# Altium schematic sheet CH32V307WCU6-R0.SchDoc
size 332 x 281 mm
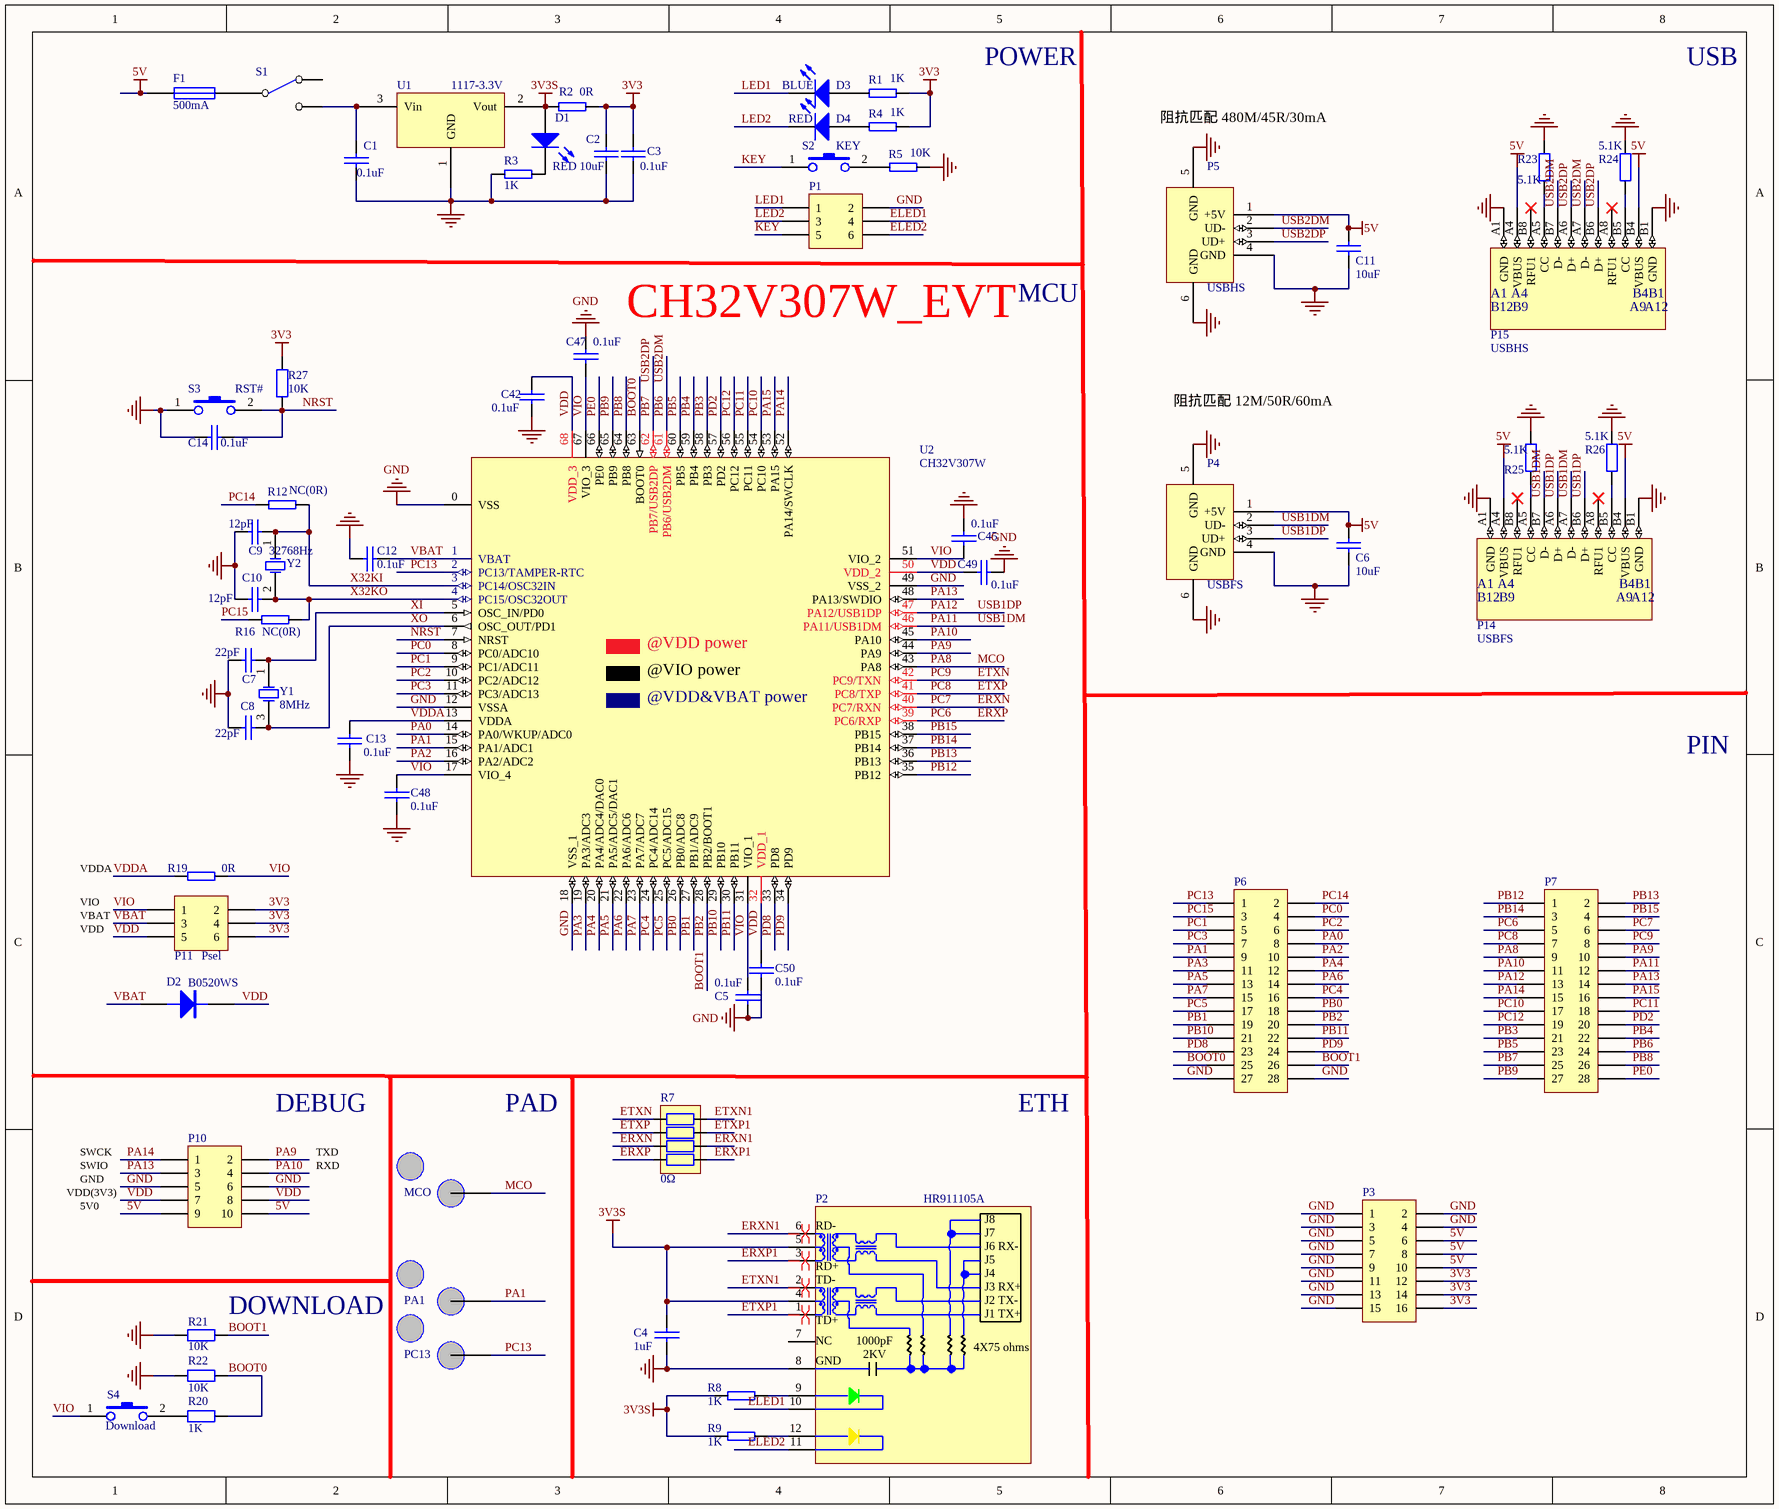
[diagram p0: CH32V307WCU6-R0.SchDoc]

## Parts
C1  0.1uF  [0603_C]
C2  10uF  [3216_C]
C3  0.1uF  [0603_C]
C4  1uF  [0603_C]
C5  0.1uF  [0603_C]
C6  10uF  [3216_C]
C7  22pF  [0603_C]
C8  22pF  [0603_C]
C9  12pF  [0603_C]
C10  12pF  [0603_C]
C11  10uF  [3216_C]
C12  0.1uF  [0603_C]
C13  0.1uF  [0603_C]
C14  0.1uF  [0603_C]
C42  0.1uF  [0603_C]
C45  0.1uF  [0603_C]
C47  0.1uF  [0603_C]
C48  0.1uF  [0603_C]
C49  0.1uF  [0603_C]
C50  0.1uF  [0603_C]
D1  RED  [0603+]
D2  B0520WS  [SOD-323]
D3  BLUE  [0603+]
D4  RED  [0603+]
F1  500mA  [0603]
MCO  Testpoint  [TESTPOINT1]  (value not drawn)
P1  IO  [IDC6-2.54mm]  (value not drawn)
P2  HR911105A  [HR911105A]
P3  Ppin  [IDC16-2.54mm]  (value not drawn)
P4  USBFS  [USBAF]
P5  USBHS  [USBAF]
P6  HEADER 14x2  [IDC28-2.54MM]  (value not drawn)
P7  HEADER 14x2  [IDC28-2.54MM]  (value not drawn)
P10  LINK  [IDC10-2.54mm]  (value not drawn)
P11  Psel  [IDC6-2.54mm]
P14  USBFS  [TYPE-C-Receptacle-2.0]
P15  USBHS  [TYPE-C-Receptacle-2.0]
PA1  Testpoint  [TESTPOINT1]  (value not drawn)
PC13  Testpoint  [TESTPOINT1]  (value not drawn)
R1  1K  [0603]
R2  0R  [0603]
R3  1K  [0603]
R4  1K  [0603]
R5  10K  [0603]
R7  0Ω  [8P4R-0603]
R8  1K  [0603]
R9  1K  [0603]
R12  NC(0R)  [0603]
R16  NC(0R)  [0603]
R19  0R  [0603]
R20  1K  [0603]
R21  10K  [0603]
R22  10K  [0603]
R23  5.1K  [0603]
R24  5.1K  [0603]
R25  5.1K  [0603]
R26  5.1K  [0603]
R27  10K  [0603]
S1  SW SPDT  [KEY2]  (value not drawn)
S2  KEY  [SMD_6.1x3.65x2.5mm-KEY]
S3  RST#  [SMD_6.1x3.65x2.5mm-KEY]
S4  Download  [SMD_6.1x3.65x2.5mm-KEY]
U1  1117-3.3V  [SOT-223]
U2  CH32V307W  [QFN68_8x8]
Y1  8MHz  [XT3225]
Y2  32768Hz  [FC-135]

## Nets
3V3: C2.1 C3.1 P3.12 P3.14 P3.16 P11.2 P11.4 P11.6 R1.1 R2.1 R4.1 R27.2
3V3S: C4.2 D1.1(A) P2.4 P2.5 R2.2 R8.1 R9.1 U1.2(Vout)
5V: C6.1 C11.1 F1.1 P3.6 P3.8 P3.10 P4.1(+5V) P5.1(+5V) P10.9 P10.10 P14.A4(VBUS) P14.B4(VBUS) P15.A4(VBUS) P15.B4(VBUS)
GND: C1.2 C2.2 C3.2 C4.1 C5.1 C6.2 C7.1 C8.1 C9.1 C10.1 C11.2 C12.1 C13.2 C14.1 C42.1 C45.2 C47.2 C48.2 C49.1 C50.2 P1.2 P2.8 P3.1 P3.2 P3.3 P3.4 P3.5 P3.7 P3.9 P3.11 P3.13 P3.15 P4.4(GND) P4.5(GND) P4.6(GND) P5.4(GND) P5.5(GND) P5.6(GND) P6.27 P6.28 P10.5 P10.6 P14.A1(GND) P14.B1(GND) P15.A1(GND) P15.B1(GND) R3.2 R5.1 R21.2 R22.2 R23.2 R24.2 R25.2 R26.2 S3.1 U1.1(GND) U2.0(VSS) U2.12(VSSA) U2.18(VSS_1) U2.49(VSS_2)
BOOT0: P6.25 R20.1 R22.1 U2.63(BOOT0)
BOOT1: P6.20 P6.26 R21.1 U2.28(PB2/BOOT1)  [also labelled PB2]
ELED1: P1.4 P2.10
ELED2: P1.6 P2.11
ERXN: P7.6 R7.3 U2.40(PC7/RXN)  [also labelled PC7]
ERXN1: P2.6 R7.6
ERXP: P7.5 R7.4 U2.39(PC6/RXP)  [also labelled PC6]
ERXP1: P2.3 R7.5
ETXN: P7.8 R7.1 U2.42(PC9/TXN)  [also labelled PC9]
ETXN1: P2.2 R7.8
ETXP: P7.7 R7.2 U2.41(PC8/TXP)  [also labelled PC8]
ETXP1: P2.1 R7.7
KEY: P1.5 S2.1
LED1: D3.2(K) P1.1
LED2: D4.2(K) P1.3
MCO: MCO.1(point) P7.9 U2.43(PA8)  [also labelled PA8]
NRST: C14.2 R27.1 S3.2 U2.7(NRST)
PA0: P6.8 U2.14(PA0/WKUP/ADC0)
PA1: P6.9 PA1.1(point) U2.15(PA1/ADC1)
PA2: P6.10 U2.16(PA2/ADC2)
PA3: P6.11 U2.19(PA3/ADC3)
PA4: P6.12 U2.20(PA4/ADC4/DAC0)
PA5: P6.13 U2.21(PA5/ADC5/DAC1)
PA6: P6.14 U2.22(PA6/ADC6)
PA7: P6.15 U2.23(PA7/ADC7)
PA9: P7.10 P10.2 U2.44(PA9)
PA10: P7.11 P10.4 U2.45(PA10)
PA11: P4.2(UD-) P7.12 P14.A7(D-) P14.B7(D-) U2.46(PA11/USB1DM)  [also labelled USB1DM]
PA12: P4.3(UD+) P7.13 P14.A6(D+) P14.B6(D+) U2.47(PA12/USB1DP)  [also labelled USB1DP]
PA13: P7.14 P10.3 U2.48(PA13/SWDIO)
PA14: P7.15 P10.1 U2.52(PA14/SWCLK)
PA15: P7.16 U2.53(PA15)
PB0: P6.18 U2.26(PB0/ADC8)
PB1: P6.19 U2.27(PB1/ADC9)
PB3: P7.21 U2.58(PB3)
PB4: P7.22 U2.59(PB4)
PB5: P7.23 U2.60(PB5)
PB6: P5.2(UD-) P7.24 P15.A7(D-) P15.B7(D-) U2.61(PB6/USB2DM)  [also labelled USB2DM]
PB7: P5.3(UD+) P7.25 P15.A6(D+) P15.B6(D+) U2.62(PB7/USB2DP)  [also labelled USB2DP]
PB8: P7.26 U2.64(PB8)
PB9: P7.27 U2.65(PB9)
PB10: P6.21 U2.29(PB10)
PB11: P6.22 U2.30(PB11)
PB12: P7.1 U2.35(PB12)
PB13: P7.2 U2.36(PB13)
PB14: P7.3 U2.37(PB14)
PB15: P7.4 U2.38(PB15)
PC0: P6.4 U2.8(PC0/ADC10)
PC1: P6.5 U2.9(PC1/ADC11)
PC2: P6.6 U2.10(PC2/ADC12)
PC3: P6.7 U2.11(PC3/ADC13)
PC4: P6.16 U2.24(PC4/ADC14)
PC5: P6.17 U2.25(PC5/ADC15)
PC10: P7.17 U2.54(PC10)
PC11: P7.18 U2.55(PC11)
PC12: P7.19 U2.56(PC12)
PC13: P6.1 PC13.1(point) U2.2(PC13/TAMPER-RTC)
PC14: P6.2 R12.1
PC15: P6.3 R16.1
PD2: P7.20 U2.57(PD2)
PD8: P6.23 U2.33(PD8)
PD9: P6.24 U2.34(PD9)
PE0: P7.28 U2.66(PE0)
VBAT: C12.2 D2.1(A) P11.3 U2.1(VBAT)
VDD: C42.2 C49.2 C50.1 D2.2(K) P10.7 P10.8 P11.5 U2.32(VDD_1) U2.50(VDD_2) U2.68(VDD_3)
VDDA: C13.1 R19.2 U2.13(VDDA)
VIO: C5.2 C45.1 C47.1 C48.1 P11.1 R19.1 S4.1 U2.17(VIO_4) U2.31(VIO_1) U2.51(VIO_2) U2.67(VIO_3)
X32KI: C9.2 R12.2 U2.3(PC14/OSC32IN) Y2.1(OSC1)
X32KO: C10.2 R16.2 U2.4(PC15/OSC32OUT) Y2.2(OSC2)
XI: C7.2 U2.5(OSC_IN/PD0) Y1.1(OSC1)
XO: C8.2 U2.6(OSC_OUT/PD1) Y1.3(OSC2)
NetC1_1: C1.1 S1.2(NC) U1.3(Vin)
NetD1_2: D1.2(K) R3.1
NetD3_1: D3.1(A) R1.2
NetD4_1: D4.1(A) R4.2
NetF1_2: F1.2 S1.1(COMMON)
NetP2_9: P2.9 R8.2
NetP2_12: P2.12 R9.2
NetP14_A5: P14.A5(CC) R25.1
NetP14_B5: P14.B5(CC) R26.1
NetP15_A5: P15.A5(CC) R23.1
NetP15_B5: P15.B5(CC) R24.1
NetR5_2: R5.2 S2.2
NetR20_2: R20.2 S4.2

Not connected (* = marked no-connect by the designer): P2 7; P14 A8(RFU1)* B8(RFU1)*; P15 A8(RFU1)* B8(RFU1)*; S1 3(NO)

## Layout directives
differential pair: ERXN1, ERXP1, ETXN1, ETXP1

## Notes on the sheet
- POWER
- USB
- 阻抗匹配 480M/45R/30mA
- MCU
- CH32V307W_EVT
- 阻抗匹配 12M/50R/60mA
- PIN
- VDDA
- VIO
- VBAT
- VDD
- (near P10) DEBUG
- PAD
- ETH
- SWCK
- SWIO
- GND
- TXD
- RXD
- VDD(3V3)
- 5V0
- (near R21) DOWNLOAD

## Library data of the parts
C1-C14 C42 C45 C47-C50 = CAP: Capacitor
D1 D3 D4 = LED0: Typical INFRARED GaAs LED
D2 = DIODE
F1 = FUSE1: Fuse
MCO PA1 PC13 = Testpoint: 测试点
P1 P11 = Header 3X2H: Header, 3-Pin, Dual row, Right Angle
P3 = Header 8X2H: Header, 8-Pin, Dual row, Right Angle
P4 P5 = USB: USB Port
P6 P7 = HEADER 14x2: Header, 14-Pin, Dual row
P10 = Header 5X2H: Header, 5-Pin, Dual row, Right Angle
P14 P15 = TYPE-C1
R1-R5 R8 R9 R12 R16 = RES
R7 = R-8P4R: 贴片网络排阻; 版权归属: 源创客
R19 = R
R20-R27 = Res2: Resistor
S2-S4 = KEY1
U2 = CH32V307W: RISC-V FPU HD-MCU, 144MHz, USB_480M, USB OTG, 1000M Ethernet MAC, 2*CAN
Y1 Y2 = XTAL: Crystal Oscillator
